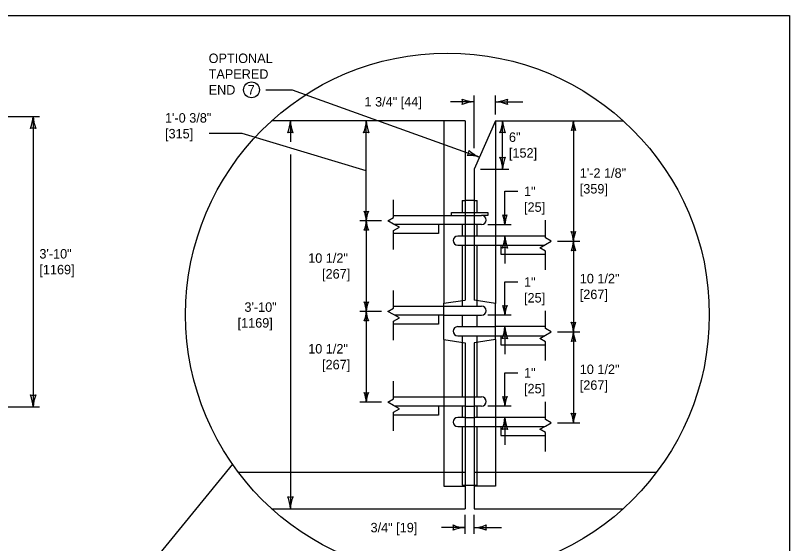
# Model space of a CAD drawing. Extents: x 49991.4 to 50021, y 49987.6 to 50011.4.
# Drawn here: x 50011.847 to 50016.75, y 49995.652 to 49998.999 of the extents above; entities that cross this region are included whole.
import ezdxf

# ---------------------------------------------------------------- set-up
doc = ezdxf.new("R2010")
doc.units = 0
for name, color, linetype in [('Level 1', 7, 'Continuous'), ('Level 2', 7, 'Continuous'), ('Level 3', 7, 'Continuous'), ('Level 4', 7, 'Continuous'), ('Level 6', 7, 'Continuous')]:
    doc.layers.add(name, color=color, linetype=linetype)

msp = doc.modelspace()

# ---------------------------------------------------------------- linework, layer by layer
at = {"layer": 'Level 1'}
for p, q in [((50014.6948, 49998.3316), (50013.4696, 49998.3316)), ((50014.6948, 49998.3316), (50014.6948, 49997.1957)), ((50014.8868, 49998.3316), (50014.7524, 49998.0246)), ((50014.8868, 49998.3316), (50015.6971, 49998.3316)), ((50014.7524, 49998.0246), (50014.7524, 49997.1957)), ((50014.7524, 49997.8274), (50014.6948, 49997.8274)), ((50014.6948, 49997.7506), (50014.7524, 49997.7506)), ((50014.6948, 49997.7315), (50014.7524, 49997.7315)), ((50014.7524, 49997.6739), (50014.6948, 49997.6739)), ((50014.7524, 49997.6014), (50014.6948, 49997.6014)), ((50014.6948, 49997.5438), (50014.7524, 49997.5438)), ((50014.5604, 49997.1752), (50014.6948, 49997.1957)), ((50014.5604, 49996.9454), (50014.5604, 49997.1752)), ((50014.6758, 49997.1928), (50014.6758, 49997.1568)), ((50014.8868, 49997.1743), (50014.7524, 49997.1957)), ((50014.7719, 49997.1568), (50014.7719, 49997.1926)), ((50014.8868, 49996.9454), (50014.8868, 49997.1743)), ((50014.5604, 49997.1568), (50014.7994, 49997.1568)), ((50014.5604, 49997.0994), (50014.7994, 49997.0994)), ((50014.6758, 49997.0994), (50014.6758, 49997.0269)), ((50014.7719, 49997.0269), (50014.7719, 49997.0994)), ((50014.6482, 49997.0269), (50014.8868, 49997.0269)), ((50014.5604, 49996.9454), (50014.6948, 49996.925)), ((50014.6482, 49996.9694), (50014.8868, 49996.9694)), ((50014.6758, 49996.9694), (50014.6758, 49996.9279)), ((50014.6948, 49996.925), (50014.6948, 49995.8733)), ((50014.8868, 49996.9454), (50014.7524, 49996.925)), ((50014.7524, 49996.925), (50014.7524, 49995.8733)), ((50014.7719, 49996.928), (50014.7719, 49996.9694)), ((50014.6948, 49996.5813), (50014.7524, 49996.5813)), ((50014.6948, 49996.5238), (50014.7524, 49996.5238)), ((50014.6948, 49996.4512), (50014.7524, 49996.4512)), ((50014.6948, 49996.3938), (50014.7524, 49996.3938)), ((50014.6948, 49996.0221), (50014.7524, 49996.0221)), ((50013.4696, 49995.8733), (50014.6948, 49995.8733)), ((50014.7524, 49995.8733), (50015.6971, 49995.8733))]:
    msp.add_line(p, q, dxfattribs=at)
msp.add_lwpolyline([(49999.3835, 49998.9992), (50016.7501, 49998.9992), (50016.7501, 49987.7988), (49999.3835, 49987.7988)], close=True, dxfattribs=at)
for centre, start, end in [((50014.7994, 49997.1281), 270, 90), ((50014.6482, 49996.9982), 90, 270)]:
    msp.add_arc(centre, 0.0287, start, end, dxfattribs=at)
at = {"layer": 'Level 2'}
msp.add_circle((50013.3418, 49998.5278), 0.05, dxfattribs=at)
at = {"layer": 'Level 3'}
for p, q in [((50013.4318, 49998.5278), (50013.5995, 49998.5278)), ((50013.5995, 49998.5278), (50014.7862, 49998.1019)), ((50014.7524, 49998.4523), (50014.6024, 49998.4523)), ((50014.7525, 49998.159), (50014.7524, 49998.4923)), ((50014.8868, 49998.3716), (50014.8868, 49998.4923)), ((50014.8868, 49998.4523), (50015.0602, 49998.4523)), ((50010.595, 49998.3586), (50011.9984, 49998.3586)), ((50011.9584, 49998.3586), (50011.9584, 49996.5186)), ((50013.5881, 49998.3316), (50013.5881, 49998.1987)), ((50014.0693, 49997.6984), (50014.0693, 49998.3316)), ((50014.9327, 49998.0246), (50014.9327, 49998.3316)), ((50015.3814, 49998.3316), (50015.3814, 49997.5684)), ((50013.5881, 49998.1187), (50013.5881, 49995.8733)), ((50014.7924, 49998.0246), (50014.9727, 49998.0246)), ((50014.9469, 49997.8848), (50015.0283, 49997.8848)), ((50014.9469, 49997.6739), (50014.9469, 49997.8848)), ((50014.166, 49997.6984), (50014.0293, 49997.6984)), ((50014.0693, 49997.6984), (50014.0693, 49997.1239)), ((50014.8394, 49997.6739), (50014.9869, 49997.6739)), ((50014.9477, 49997.6014), (50014.9477, 49997.428)), ((50015.2812, 49997.5684), (50015.4214, 49997.5684)), ((50015.3814, 49997.5684), (50015.3814, 49996.9938)), ((50014.9473, 49997.31), (50015.0283, 49997.31)), ((50014.9473, 49997.0994), (50014.9473, 49997.31)), ((50014.166, 49997.1239), (50014.0293, 49997.1239)), ((50014.0693, 49997.1239), (50014.0693, 49996.5484)), ((50014.9873, 49997.0994), (50014.8394, 49997.0994)), ((50014.9473, 49997.0269), (50014.9473, 49996.8535)), ((50015.2812, 49996.9938), (50015.4214, 49996.9938)), ((50015.3814, 49996.9938), (50015.3814, 49996.4183)), ((50014.9473, 49996.7343), (50015.0283, 49996.7343)), ((50014.9473, 49996.5238), (50014.9473, 49996.7343)), ((50014.166, 49996.5484), (50014.0293, 49996.5484)), ((50011.046, 49996.5186), (50011.9984, 49996.5186)), ((50014.9873, 49996.5238), (50014.8394, 49996.5238)), ((50014.9473, 49996.4512), (50014.9473, 49996.2778)), ((50015.2812, 49996.4182), (50015.4214, 49996.4183)), ((50013.221, 49996.1563), (50012.7333, 49995.5574)), ((50014.6948, 49995.7133), (50014.6948, 49995.8333)), ((50014.7523, 49995.7133), (50014.7523, 49995.8333)), ((50014.6948, 49995.7533), (50014.5448, 49995.7533)), ((50014.7523, 49995.7533), (50014.9257, 49995.7533))]:
    msp.add_line(p, q, dxfattribs=at)
msp.add_lwpolyline([(50014.0693, 49998.015), (50013.2824, 49998.2501), (50013.0745, 49998.2501)], dxfattribs=at)
msp.add_circle((50014.5834, 49997.1025), 1.6587, dxfattribs=at)
for centre, radius, start, end in [((50014.7616, 49998.6745), 0.2223, 247.456, 267.6395), ((50014.6242, 49998.4523), 0.0548, 342.1388, 17.8612), ((50014.7639, 49998.2196), 0.233, 92.8273, 112.0772), ((50014.8753, 49998.685), 0.233, 272.8273, 292.0772), ((50014.8776, 49998.2302), 0.2223, 67.456, 87.6395), ((50015.015, 49998.4523), 0.0548, 162.1388, 197.8612), ((50011.7362, 49998.3678), 0.2223, 337.456, 357.6395), ((50012.1911, 49998.3701), 0.233, 182.8273, 202.0772), ((50013.366, 49998.3408), 0.2223, 337.456, 357.6395), ((50013.8208, 49998.3431), 0.233, 182.8273, 202.0772), ((50013.8472, 49998.3408), 0.2223, 337.456, 357.6395), ((50014.302, 49998.3431), 0.233, 182.8273, 202.0772), ((50014.7105, 49998.3408), 0.2223, 337.456, 357.6395), ((50015.1654, 49998.3431), 0.233, 182.8273, 202.0772), ((50015.2037, 49998.339), 0.1779, 337.456, 357.6395), ((50015.5675, 49998.3408), 0.1864, 182.8273, 202.0772), ((50011.9584, 49998.2304), 0.0548, 72.1388, 107.8612), ((50013.5881, 49998.2034), 0.0548, 72.1388, 107.8612), ((50014.0693, 49998.2034), 0.0548, 72.1388, 107.8612), ((50014.9327, 49998.2034), 0.0548, 72.1388, 107.8612), ((50015.3814, 49998.2291), 0.0438, 72.1388, 107.8612), ((50014.6655, 49998.1452), 0.0548, 322.3948, 358.1171), ((50014.7184, 49997.8789), 0.233, 73.0833, 92.3331), ((50014.8699, 49998.3078), 0.2223, 227.712, 247.8955), ((50014.9327, 49998.1528), 0.0548, 252.1388, 287.8612), ((50014.7, 49998.0131), 0.233, 2.8273, 22.0772), ((50015.1548, 49998.0154), 0.2223, 157.456, 177.6395), ((50014.0693, 49997.801), 0.0438, 252.1388, 287.8612), ((50013.8831, 49997.6892), 0.1864, 2.8273, 22.0772), ((50014.247, 49997.6911), 0.1779, 157.456, 177.6395), ((50014.9469, 49997.7765), 0.0438, 252.1388, 287.8612), ((50014.7607, 49997.6647), 0.1864, 2.8273, 22.0772), ((50015.1246, 49997.6666), 0.1779, 157.456, 177.6395), ((50013.8916, 49997.7058), 0.1779, 337.456, 357.6395), ((50014.2555, 49997.7076), 0.1864, 182.8273, 202.0772), ((50014.0693, 49997.5959), 0.0438, 72.1388, 107.8612), ((50015.3814, 49997.671), 0.0438, 252.1388, 287.8612), ((50015.1952, 49997.5592), 0.1864, 2.8273, 22.0772), ((50015.5591, 49997.5611), 0.1779, 157.456, 177.6395), ((50014.7256, 49997.6106), 0.2223, 337.456, 357.6395), ((50015.1805, 49997.6129), 0.233, 182.8273, 202.0772), ((50015.2037, 49997.5758), 0.1779, 337.456, 357.6395), ((50015.5675, 49997.5776), 0.1864, 182.8273, 202.0772), ((50014.9477, 49997.4732), 0.0548, 72.1388, 107.8612), ((50015.3814, 49997.4659), 0.0438, 72.1388, 107.8612), ((50014.0693, 49997.2264), 0.0438, 252.1388, 287.8612), ((50013.8831, 49997.1147), 0.1864, 2.8273, 22.0772), ((50014.247, 49997.1165), 0.1779, 157.456, 177.6395), ((50013.8916, 49997.1312), 0.1779, 337.456, 357.6395), ((50014.2555, 49997.1331), 0.1864, 182.8273, 202.0772), ((50014.9473, 49997.202), 0.0438, 252.1388, 287.8612), ((50014.7611, 49997.0902), 0.1864, 2.8273, 22.0772), ((50015.125, 49997.0921), 0.1779, 157.456, 177.6395), ((50014.0693, 49997.0213), 0.0438, 72.1388, 107.8612), ((50014.7252, 49997.0361), 0.2223, 337.456, 357.6395), ((50015.18, 49997.0384), 0.233, 182.8273, 202.0772), ((50015.3814, 49997.0964), 0.0438, 252.1388, 287.8612), ((50015.1952, 49996.9846), 0.1864, 2.8273, 22.0772), ((50015.5591, 49996.9865), 0.1779, 157.456, 177.6395), ((50015.2037, 49997.0011), 0.1779, 337.456, 357.6395), ((50015.5675, 49997.003), 0.1864, 182.8273, 202.0772), ((50014.9473, 49996.8987), 0.0548, 72.1388, 107.8612), ((50015.3814, 49996.8912), 0.0438, 72.1388, 107.8612), ((50011.9584, 49996.6469), 0.0548, 252.1388, 287.8612), ((50011.7257, 49996.5071), 0.233, 2.8273, 22.0772), ((50012.1805, 49996.5095), 0.2223, 157.456, 177.6395), ((50014.0693, 49996.6509), 0.0438, 252.1388, 287.8612), ((50013.8831, 49996.5392), 0.1864, 2.8273, 22.0772), ((50014.247, 49996.541), 0.1779, 157.456, 177.6395), ((50014.9473, 49996.6264), 0.0438, 252.1388, 287.8612), ((50014.7611, 49996.5146), 0.1864, 2.8273, 22.0772), ((50015.125, 49996.5165), 0.1779, 157.456, 177.6395), ((50014.7252, 49996.4604), 0.2223, 337.456, 357.6395), ((50015.18, 49996.4627), 0.233, 182.8273, 202.0772), ((50015.3814, 49996.5208), 0.0438, 252.1388, 287.8612), ((50015.1952, 49996.4091), 0.1864, 2.8273, 22.0772), ((50015.5591, 49996.4109), 0.1779, 157.456, 177.6395), ((50014.9473, 49996.323), 0.0548, 72.1388, 107.8612), ((50013.5881, 49996.0015), 0.0548, 252.1388, 287.8612), ((50013.3554, 49995.8618), 0.233, 2.8273, 22.0772), ((50013.8103, 49995.8641), 0.2223, 157.456, 177.6395), ((50014.704, 49995.9754), 0.2223, 247.456, 267.6395), ((50014.5666, 49995.7533), 0.0548, 342.1388, 17.8612), ((50014.7063, 49995.5206), 0.233, 92.8273, 112.0772), ((50014.7408, 49995.986), 0.233, 272.8273, 292.0772), ((50014.7431, 49995.5312), 0.2223, 67.456, 87.6395), ((50014.8805, 49995.7533), 0.0548, 162.1388, 197.8612)]:
    msp.add_arc(centre, radius, start, end, dxfattribs=at)
at = {"layer": 'Level 4'}
for p, q in [((50014.5604, 49998.3316), (50014.5604, 49997.1752)), ((50014.8868, 49998.3316), (50014.8868, 49997.1743)), ((50014.6758, 49997.8274), (50014.6948, 49997.8274)), ((50014.6758, 49997.8274), (50014.6758, 49997.7506)), ((50014.7524, 49997.8274), (50014.7719, 49997.8274)), ((50014.7719, 49997.7506), (50014.7719, 49997.8274)), ((50014.2424, 49997.7315), (50014.6948, 49997.7315)), ((50014.6084, 49997.7315), (50014.6084, 49997.7506)), ((50014.6084, 49997.7506), (50014.6948, 49997.7506)), ((50014.7524, 49997.7506), (50014.8388, 49997.7506)), ((50014.7524, 49997.7315), (50014.7994, 49997.7315)), ((50014.8388, 49997.7315), (50014.7994, 49997.7315)), ((50014.8388, 49997.7506), (50014.8388, 49997.7315)), ((50014.6951, 49997.6739), (50014.2484, 49997.6739)), ((50014.5256, 49997.6739), (50014.5256, 49997.6164)), ((50014.6758, 49997.6739), (50014.6758, 49997.6014)), ((50014.7994, 49997.6739), (50014.7526, 49997.6739)), ((50014.7719, 49997.6014), (50014.7719, 49997.6739)), ((50014.5256, 49997.6164), (50014.2424, 49997.6164)), ((50014.6948, 49997.6014), (50014.6483, 49997.6014)), ((50015.205, 49997.6014), (50014.7524, 49997.6014)), ((50014.6483, 49997.5438), (50014.6948, 49997.5438)), ((50014.6758, 49997.5438), (50014.6758, 49997.1928)), ((50014.7524, 49997.5438), (50015.1986, 49997.5438)), ((50014.7719, 49997.1926), (50014.7719, 49997.5438)), ((50014.9216, 49997.5438), (50014.9216, 49997.4866)), ((50014.9216, 49997.4866), (50015.205, 49997.4866)), ((50014.2424, 49997.1568), (50014.5604, 49997.1568)), ((50014.5604, 49997.0994), (50014.2486, 49997.0994)), ((50014.5256, 49997.0994), (50014.5256, 49997.0419)), ((50014.5256, 49997.0419), (50014.2424, 49997.0419)), ((50015.205, 49997.0269), (50014.8868, 49997.0269)), ((50014.5604, 49996.9454), (50014.5604, 49996.017)), ((50014.6758, 49996.9279), (50014.6758, 49996.5813)), ((50014.7719, 49996.5813), (50014.7719, 49996.928)), ((50014.8868, 49996.9694), (50015.1991, 49996.9694)), ((50014.8868, 49996.9454), (50014.8868, 49996.017)), ((50014.9216, 49996.9694), (50014.9216, 49996.9118)), ((50014.9216, 49996.9118), (50015.205, 49996.9118)), ((50014.2424, 49996.5813), (50014.6948, 49996.5813)), ((50014.7524, 49996.5813), (50014.7994, 49996.5813)), ((50014.6948, 49996.5238), (50014.2486, 49996.5238)), ((50014.5256, 49996.5238), (50014.5256, 49996.4663)), ((50014.6758, 49996.5238), (50014.6758, 49996.4512)), ((50014.7994, 49996.5238), (50014.7524, 49996.5238)), ((50014.7719, 49996.4512), (50014.7719, 49996.5238)), ((50014.5256, 49996.4663), (50014.2424, 49996.4663)), ((50014.6948, 49996.4512), (50014.6483, 49996.4512)), ((50015.205, 49996.4512), (50014.7524, 49996.4512)), ((50014.6483, 49996.3938), (50014.6948, 49996.3938)), ((50014.6758, 49996.3938), (50014.6758, 49996.0221)), ((50014.7524, 49996.3938), (50015.199, 49996.3938)), ((50014.7719, 49996.0221), (50014.7719, 49996.3938)), ((50014.9216, 49996.3938), (50014.9216, 49996.3363)), ((50014.9216, 49996.3363), (50015.205, 49996.3363)), ((50014.6948, 49996.103), (50013.2596, 49996.103)), ((50015.9071, 49996.103), (50014.7526, 49996.103)), ((50014.5604, 49996.017), (50014.6948, 49996.017)), ((50014.6758, 49996.0221), (50014.6948, 49996.0221)), ((50014.7524, 49996.0221), (50014.7719, 49996.0221)), ((50014.8868, 49996.017), (50014.7524, 49996.017))]:
    msp.add_line(p, q, dxfattribs=at)
for centre, radius, start, end in [((50014.7994, 49997.7027), 0.0288, 270, 90), ((50014.6483, 49997.5726), 0.0288, 90, 270), ((50014.7994, 49996.5526), 0.0288, 270, 90), ((50014.6483, 49996.4225), 0.0287, 90, 270)]:
    msp.add_arc(centre, radius, start, end, dxfattribs=at)
at = {"layer": 'Level 6'}
for p, q in [((50014.2424, 49997.7194), (50014.2424, 49997.8315)), ((50014.206, 49997.6984), (50014.2424, 49997.7194)), ((50014.2424, 49997.6774), (50014.206, 49997.6984)), ((50014.2786, 49997.6566), (50014.2424, 49997.6774)), ((50015.205, 49997.5894), (50015.205, 49997.7014)), ((50014.2424, 49997.6356), (50014.2786, 49997.6566)), ((50014.2424, 49997.5164), (50014.2424, 49997.6356)), ((50015.2412, 49997.5684), (50015.205, 49997.5894)), ((50015.205, 49997.5475), (50015.2412, 49997.5684)), ((50015.1686, 49997.5265), (50015.205, 49997.5475)), ((50015.205, 49997.5055), (50015.1686, 49997.5265)), ((50015.205, 49997.3866), (50015.205, 49997.5055)), ((50014.2424, 49997.1449), (50014.2424, 49997.2568)), ((50014.206, 49997.1238), (50014.2424, 49997.1449)), ((50014.2424, 49997.103), (50014.206, 49997.1238)), ((50015.205, 49997.0148), (50015.205, 49997.1269)), ((50014.2786, 49997.0821), (50014.2424, 49997.103)), ((50014.2424, 49997.061), (50014.2786, 49997.0821)), ((50014.2424, 49996.9419), (50014.2424, 49997.061)), ((50015.2412, 49996.9938), (50015.205, 49997.0148)), ((50015.205, 49996.9728), (50015.2412, 49996.9938)), ((50015.1686, 49996.9519), (50015.205, 49996.9728)), ((50015.205, 49996.931), (50015.1686, 49996.9519)), ((50015.205, 49996.8118), (50015.205, 49996.931)), ((50014.2424, 49996.5691), (50014.2424, 49996.6813)), ((50014.206, 49996.5483), (50014.2424, 49996.5691)), ((50014.2424, 49996.5274), (50014.206, 49996.5483)), ((50015.205, 49996.4393), (50015.205, 49996.5512)), ((50014.2786, 49996.5064), (50014.2424, 49996.5274)), ((50014.2424, 49996.4854), (50014.2786, 49996.5064)), ((50014.2424, 49996.3663), (50014.2424, 49996.4854)), ((50015.2412, 49996.4182), (50015.205, 49996.4393)), ((50015.1686, 49996.3763), (50015.205, 49996.3973)), ((50015.205, 49996.3973), (50015.2412, 49996.4182)), ((50015.205, 49996.3554), (50015.1686, 49996.3763)), ((50015.205, 49996.2363), (50015.205, 49996.3554))]:
    msp.add_line(p, q, dxfattribs=at)

# ---------------------------------------------------------------- texts
at = {"layer": 'Level 2'}
for s, p in [('OPTIONAL', (50013.0705, 49998.6978)), ('TAPERED ', (50013.0705, 49998.5978)), ('END', (50013.0705, 49998.4978)), ('7', (50013.318, 49998.4978)), ('1 3/4" [44]', (50014.0579, 49998.4223)), ('1\'-0 3/8"', (50012.7941, 49998.3201)), ('[315]', (50012.7941, 49998.2201)), ('6"', (50014.9727, 49998.1981)), ('[152]', (50014.9727, 49998.0981)), ('1\'-2 1/8"', (50015.4214, 49997.9706)), ('1"', (50015.0683, 49997.8548)), ('[359]', (50015.4214, 49997.8706)), ('[25]', (50015.0683, 49997.7548)), ('3\'-10"', (50011.9984, 49997.4587)), ('10 1/2"', (50013.7013, 49997.4317)), ('[1169]', (50011.9984, 49997.3587)), ('[267]', (50013.7889, 49997.3317)), ('1"', (50015.0683, 49997.28)), ('10 1/2"', (50015.4214, 49997.3016)), ('[25]', (50015.0683, 49997.18)), ('[267]', (50015.4214, 49997.2016)), ('3\'-10"', (50013.2973, 49997.1208)), ('[1169]', (50013.2538, 49997.0208)), ('10 1/2"', (50013.7013, 49996.8567)), ('[267]', (50013.7889, 49996.7567)), ('10 1/2"', (50015.4214, 49996.7266)), ('1"', (50015.0683, 49996.7043)), ('[267]', (50015.4214, 49996.6266)), ('[25]', (50015.0683, 49996.6043)), ('3/4" [19]', (50014.0962, 49995.7233))]:
    msp.add_text(s, height=0.06, dxfattribs=at).set_placement(p)

doc.saveas('drawing.dxf')
